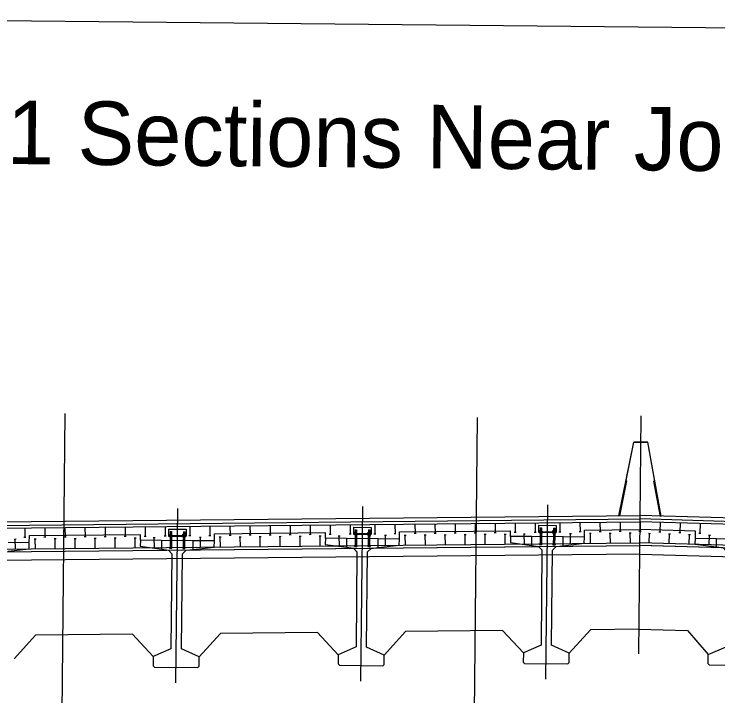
# Model space of a CAD drawing. Extents: x 632047 to 632524, y 378118 to 378491.
# Drawn here: x 632347.97 to 632381.26, y 378202.06 to 378234.31 of the extents above; entities that cross this region are included whole.
import ezdxf

# ---------------------------------------------------------------- set-up
doc = ezdxf.new("R2010")
doc.units = 0
for name, color, linetype in [('B_Boring', 7, 'Continuous'), ('B_Boring Annot', 7, 'Continuous'), ('B_No_Plot', 7, 'Continuous'), ('D_FEMA A', 7, 'Continuous'), ('R_Border_Divider', 7, 'Continuous'), ('R_Proposed Const Limits Cut', 7, 'Continuous'), ('R_Proposed Const Limits Fill', 7, 'Continuous'), ('R_Road Edge of Shoulder', 7, 'Continuous'), ('R_Shade Removal', 7, 'Continuous'), ('USACE_Easement', 7, 'Continuous'), ('USACE_Owned_Permited to Fort Chaffee', 7, 'Continuous')]:
    doc.layers.add(name, color=color, linetype=linetype)

msp = doc.modelspace()

# ---------------------------------------------------------------- linework, layer by layer
at = {"layer": 'B_Boring'}
for p, q in [((632376.625, 378210.569), (632376.958, 378212.231)), ((632376.918, 378212.239), (632376.958, 378212.231)), ((632378.28, 378212.226), (632378.239, 378212.218)), ((632378.539, 378210.55), (632378.239, 378212.218)), ((632336.245, 378210.015), (632377.581, 378210.428)), ((632336.493, 378210.184), (632377.582, 378210.597)), ((632418.9, 378209.19), (632377.581, 378210.428)), ((632418.655, 378209.364), (632377.583, 378210.597)), ((632336.575, 378209.887), (632377.579, 378210.299)), ((632372.783, 378210.127), (632372.78, 378209.797)), ((632372.783, 378210.127), (632373.616, 378210.118)), ((632373.616, 378210.118), (632373.613, 378209.789)), ((632418.567, 378209.069), (632377.58, 378210.299)), ((632355.28, 378209.951), (632355.277, 378209.621)), ((632355.28, 378209.951), (632356.114, 378209.942)), ((632356.114, 378209.942), (632356.11, 378209.613)), ((632364.032, 378210.039), (632364.028, 378209.709)), ((632364.032, 378210.039), (632364.865, 378210.03)), ((632364.075, 378209.757), (632364.197, 378209.756)), ((632364.075, 378209.742), (632364.075, 378209.757)), ((632364.084, 378209.796), (632364.188, 378209.795)), ((632364.084, 378209.757), (632364.084, 378209.796)), ((632364.188, 378209.756), (632364.188, 378209.795)), ((632364.197, 378209.741), (632364.197, 378209.756)), ((632364.7, 378209.751), (632364.822, 378209.75)), ((632364.7, 378209.736), (632364.7, 378209.751)), ((632364.709, 378209.79), (632364.813, 378209.789)), ((632364.709, 378209.751), (632364.709, 378209.79)), ((632364.813, 378209.75), (632364.813, 378209.789)), ((632364.822, 378209.735), (632364.822, 378209.75)), ((632364.865, 378210.03), (632364.862, 378209.701)), ((632372.78, 378209.831), (632373.613, 378209.822)), ((632372.78, 378209.797), (632373.613, 378209.789)), ((632372.826, 378209.797), (632372.825, 378209.782)), ((632372.825, 378209.782), (632372.948, 378209.781)), ((632372.826, 378209.845), (632372.949, 378209.844)), ((632372.826, 378209.83), (632372.826, 378209.845)), ((632372.826, 378209.83), (632372.948, 378209.829)), ((632372.826, 378209.797), (632372.948, 378209.796)), ((632372.835, 378209.782), (632372.834, 378209.743)), ((632372.835, 378209.845), (632372.836, 378209.884)), ((632372.836, 378209.884), (632372.94, 378209.883)), ((632372.939, 378209.781), (632372.938, 378209.742)), ((632372.939, 378209.844), (632372.94, 378209.883)), ((632372.948, 378209.829), (632372.949, 378209.844)), ((632372.948, 378209.796), (632372.948, 378209.781)), ((632373.451, 378209.791), (632373.45, 378209.776)), ((632373.45, 378209.776), (632373.573, 378209.775)), ((632373.451, 378209.839), (632373.573, 378209.838)), ((632373.451, 378209.824), (632373.451, 378209.839)), ((632373.451, 378209.824), (632373.573, 378209.823)), ((632373.451, 378209.791), (632373.573, 378209.789)), ((632373.46, 378209.776), (632373.459, 378209.737)), ((632373.46, 378209.839), (632373.461, 378209.878)), ((632373.461, 378209.878), (632373.565, 378209.877)), ((632373.564, 378209.775), (632373.563, 378209.736)), ((632373.564, 378209.838), (632373.565, 378209.877)), ((632373.573, 378209.823), (632373.573, 378209.838)), ((632373.573, 378209.789), (632373.573, 378209.775)), ((632355.277, 378209.655), (632356.111, 378209.646)), ((632355.277, 378209.621), (632356.11, 378209.613)), ((632355.323, 378209.669), (632355.446, 378209.668)), ((632355.323, 378209.654), (632355.323, 378209.669)), ((632355.323, 378209.654), (632355.446, 378209.653)), ((632355.323, 378209.621), (632355.323, 378209.606)), ((632355.323, 378209.621), (632355.445, 378209.62)), ((632355.323, 378209.606), (632355.445, 378209.605)), ((632355.332, 378209.606), (632355.332, 378209.567)), ((632355.332, 378209.567), (632355.436, 378209.566)), ((632355.333, 378209.708), (632355.437, 378209.707)), ((632355.333, 378209.669), (632355.333, 378209.708)), ((632355.436, 378209.605), (632355.436, 378209.566)), ((632355.437, 378209.668), (632355.437, 378209.707)), ((632355.445, 378209.62), (632355.445, 378209.605)), ((632355.446, 378209.653), (632355.446, 378209.668)), ((632355.948, 378209.663), (632356.071, 378209.662)), ((632355.948, 378209.648), (632355.948, 378209.663)), ((632355.948, 378209.648), (632356.071, 378209.647)), ((632355.948, 378209.615), (632355.948, 378209.6)), ((632355.948, 378209.615), (632356.07, 378209.613)), ((632355.948, 378209.6), (632356.07, 378209.599)), ((632355.957, 378209.6), (632355.957, 378209.561)), ((632355.957, 378209.561), (632356.061, 378209.56)), ((632355.958, 378209.702), (632356.062, 378209.701)), ((632355.958, 378209.663), (632355.958, 378209.702)), ((632356.061, 378209.599), (632356.061, 378209.56)), ((632356.062, 378209.662), (632356.062, 378209.701)), ((632356.07, 378209.613), (632356.07, 378209.599)), ((632356.071, 378209.647), (632356.071, 378209.662)), ((632364.028, 378209.709), (632364.862, 378209.701)), ((632364.029, 378209.743), (632364.862, 378209.734)), ((632364.074, 378209.709), (632364.074, 378209.694)), ((632364.074, 378209.709), (632364.197, 378209.708)), ((632364.074, 378209.694), (632364.197, 378209.693)), ((632364.075, 378209.742), (632364.197, 378209.741)), ((632364.083, 378209.694), (632364.083, 378209.655)), ((632364.083, 378209.655), (632364.187, 378209.654)), ((632364.187, 378209.693), (632364.187, 378209.654)), ((632364.197, 378209.708), (632364.197, 378209.693)), ((632364.699, 378209.703), (632364.699, 378209.688)), ((632364.699, 378209.703), (632364.822, 378209.701)), ((632364.699, 378209.688), (632364.822, 378209.687)), ((632364.7, 378209.736), (632364.822, 378209.735)), ((632364.708, 378209.688), (632364.708, 378209.649)), ((632364.708, 378209.649), (632364.812, 378209.648)), ((632364.812, 378209.687), (632364.812, 378209.648)), ((632364.822, 378209.701), (632364.822, 378209.687)), ((632372.834, 378209.743), (632372.938, 378209.742)), ((632373.459, 378209.737), (632373.563, 378209.736)), ((632336.587, 378208.768), (632377.593, 378209.178)), ((632336.591, 378208.892), (632377.569, 378209.304)), ((632336.593, 378208.768), (632377.568, 378209.18)), ((632418.533, 378207.951), (632377.543, 378209.178)), ((632418.527, 378207.951), (632377.568, 378209.18)), ((632418.532, 378208.075), (632377.569, 378209.304))]:
    msp.add_line(p, q, dxfattribs=at)
at = {"layer": 'B_Boring Annot'}
for p, q in [((632376.582, 378210.569), (632377.284, 378214.062)), ((632376.586, 378210.587), (632377.284, 378214.062)), ((632376.586, 378210.587), (632377.284, 378214.062)), ((632377.284, 378214.062), (632377.95, 378214.055)), ((632377.284, 378214.062), (632377.95, 378214.055)), ((632377.95, 378214.055), (632377.284, 378214.062)), ((632377.95, 378214.055), (632377.284, 378214.062)), ((632377.95, 378214.055), (632377.284, 378214.062)), ((632377.95, 378214.055), (632377.284, 378214.062)), ((632377.284, 378214.062), (632377.95, 378214.055)), ((632377.95, 378214.055), (632377.284, 378214.062)), ((632377.95, 378214.055), (632377.284, 378214.062)), ((632377.284, 378214.062), (632377.95, 378214.055)), ((632377.284, 378214.062), (632377.95, 378214.055)), ((632377.284, 378214.062), (632377.95, 378214.055)), ((632377.284, 378214.062), (632377.95, 378214.055)), ((632378.579, 378210.567), (632377.95, 378214.055)), ((632378.582, 378210.549), (632377.95, 378214.055)), ((632378.579, 378210.567), (632377.95, 378214.055)), ((632378.579, 378210.567), (632377.95, 378214.055)), ((632378.582, 378210.549), (632377.95, 378214.055)), ((632336.576, 378210.185), (632377.582, 378210.597)), ((632418.572, 378209.367), (632377.582, 378210.597)), ((632366.486, 378205.101), (632365.475, 378203.986)), ((632371.07, 378205.148), (632366.486, 378205.101)), ((632372.059, 378204.096), (632371.07, 378205.148)), ((632375.237, 378205.189), (632374.226, 378204.074)), ((632377.529, 378205.212), (632375.237, 378205.189)), ((632377.528, 378205.212), (632379.819, 378205.144)), ((632379.819, 378205.144), (632380.808, 378204.009)), ((632348.983, 378204.925), (632347.972, 378203.81)), ((632353.567, 378204.971), (632348.983, 378204.925)), ((632354.557, 378203.92), (632353.567, 378204.971)), ((632357.734, 378205.013), (632356.723, 378203.898)), ((632362.318, 378205.059), (632357.734, 378205.013)), ((632363.308, 378204.008), (632362.318, 378205.059))]:
    msp.add_line(p, q, dxfattribs=at)
at = {"layer": 'B_No_Plot'}
for p, q in [((632356.285, 378210.085), (632356.289, 378209.627)), ((632357.233, 378210.094), (632357.237, 378209.637)), ((632358.181, 378210.104), (632358.185, 378209.646)), ((632359.129, 378210.113), (632359.134, 378209.656)), ((632360.077, 378210.123), (632360.082, 378209.665)), ((632361.025, 378210.132), (632361.03, 378209.675)), ((632361.973, 378210.142), (632361.978, 378209.684)), ((632362.921, 378210.152), (632362.926, 378209.694)), ((632363.869, 378210.161), (632363.874, 378209.703)), ((632365.036, 378210.173), (632365.041, 378209.715)), ((632365.984, 378210.182), (632365.989, 378209.725)), ((632366.932, 378210.192), (632366.937, 378209.734)), ((632367.88, 378210.201), (632367.885, 378209.744)), ((632368.828, 378210.211), (632368.833, 378209.753)), ((632369.776, 378210.22), (632369.781, 378209.763)), ((632370.725, 378210.23), (632370.729, 378209.772)), ((632371.673, 378210.24), (632371.677, 378209.782)), ((632372.621, 378210.249), (632372.625, 378209.791)), ((632373.787, 378210.261), (632373.792, 378209.803)), ((632374.735, 378210.27), (632374.74, 378209.813)), ((632375.683, 378210.28), (632375.688, 378209.822)), ((632376.632, 378210.289), (632376.636, 378209.832)), ((632377.579, 378210.299), (632377.565, 378209.841)), ((632377.579, 378210.299), (632377.565, 378209.841)), ((632377.58, 378210.299), (632377.584, 378209.841)), ((632377.58, 378210.299), (632377.584, 378209.841)), ((632378.527, 378210.271), (632378.513, 378209.813)), ((632379.475, 378210.242), (632379.461, 378209.785)), ((632380.422, 378210.214), (632380.409, 378209.756)), ((632348.481, 378210.006), (632348.486, 378209.549)), ((632349.43, 378210.016), (632349.434, 378209.558)), ((632350.378, 378210.025), (632350.382, 378209.568)), ((632351.326, 378210.035), (632351.33, 378209.577)), ((632352.274, 378210.044), (632352.278, 378209.587)), ((632353.222, 378210.054), (632353.227, 378209.596)), ((632354.17, 378210.064), (632354.175, 378209.606)), ((632355.118, 378210.073), (632355.123, 378209.615)), ((632367.932, 378209.744), (632367.838, 378209.743)), ((632368.88, 378209.754), (632368.786, 378209.753)), ((632369.828, 378209.763), (632369.734, 378209.762)), ((632370.776, 378209.773), (632370.682, 378209.772)), ((632371.724, 378209.782), (632371.63, 378209.781)), ((632372.672, 378209.792), (632372.578, 378209.791)), ((632373.839, 378209.804), (632373.745, 378209.803)), ((632374.787, 378209.813), (632374.693, 378209.812)), ((632375.735, 378209.823), (632375.641, 378209.822)), ((632376.219, 378209.748), (632376.126, 378209.747)), ((632376.177, 378209.29), (632376.173, 378209.748)), ((632376.683, 378209.832), (632376.589, 378209.831)), ((632377.164, 378209.758), (632377.07, 378209.757)), ((632377.121, 378209.3), (632377.117, 378209.757)), ((632377.519, 378209.843), (632377.612, 378209.84)), ((632377.519, 378209.843), (632377.612, 378209.84)), ((632377.631, 378209.842), (632377.537, 378209.841)), ((632377.631, 378209.842), (632377.537, 378209.841)), ((632377.984, 378209.75), (632378.078, 378209.747)), ((632378.017, 378209.291), (632378.031, 378209.748)), ((632378.466, 378209.814), (632378.56, 378209.812)), ((632379.414, 378209.786), (632379.508, 378209.783)), ((632380.362, 378209.757), (632380.455, 378209.755)), ((632348.077, 378209.465), (632347.983, 378209.464)), ((632348.035, 378209.007), (632348.03, 378209.465)), ((632348.533, 378209.549), (632348.439, 378209.548)), ((632349.021, 378209.475), (632348.928, 378209.474)), ((632348.979, 378209.017), (632348.974, 378209.474)), ((632349.481, 378209.559), (632349.387, 378209.558)), ((632349.965, 378209.484), (632349.872, 378209.483)), ((632349.923, 378209.026), (632349.919, 378209.484)), ((632350.429, 378209.568), (632350.335, 378209.567)), ((632350.91, 378209.494), (632350.816, 378209.493)), ((632350.867, 378209.036), (632350.863, 378209.493)), ((632351.377, 378209.578), (632351.283, 378209.577)), ((632351.854, 378209.503), (632351.76, 378209.502)), ((632351.812, 378209.045), (632351.807, 378209.503)), ((632352.325, 378209.587), (632352.232, 378209.586)), ((632352.798, 378209.513), (632352.704, 378209.512)), ((632352.756, 378209.055), (632352.751, 378209.512)), ((632353.273, 378209.597), (632353.18, 378209.596)), ((632353.742, 378209.522), (632353.648, 378209.521)), ((632353.7, 378209.064), (632353.695, 378209.522)), ((632354.221, 378209.606), (632354.128, 378209.605)), ((632354.65, 378209.531), (632354.557, 378209.531)), ((632354.608, 378209.073), (632354.603, 378209.531)), ((632355.17, 378209.616), (632355.076, 378209.615)), ((632356.336, 378209.628), (632356.242, 378209.627)), ((632356.828, 378209.553), (632356.735, 378209.552)), ((632356.786, 378209.095), (632356.782, 378209.553)), ((632357.284, 378209.637), (632357.19, 378209.636)), ((632357.773, 378209.563), (632357.679, 378209.562)), ((632357.73, 378209.105), (632357.726, 378209.562)), ((632358.232, 378209.647), (632358.139, 378209.646)), ((632358.717, 378209.572), (632358.623, 378209.571)), ((632358.675, 378209.114), (632358.67, 378209.572)), ((632359.18, 378209.656), (632359.087, 378209.655)), ((632359.661, 378209.582), (632359.567, 378209.581)), ((632359.619, 378209.124), (632359.614, 378209.581)), ((632360.129, 378209.666), (632360.035, 378209.665)), ((632360.605, 378209.591), (632360.511, 378209.59)), ((632360.563, 378209.133), (632360.558, 378209.591)), ((632361.077, 378209.675), (632360.983, 378209.674)), ((632361.549, 378209.601), (632361.456, 378209.6)), ((632361.507, 378209.143), (632361.502, 378209.6)), ((632362.025, 378209.685), (632361.931, 378209.684)), ((632362.494, 378209.61), (632362.4, 378209.609)), ((632362.451, 378209.152), (632362.447, 378209.61)), ((632362.973, 378209.694), (632362.879, 378209.693)), ((632363.402, 378209.619), (632363.308, 378209.619)), ((632363.359, 378209.161), (632363.355, 378209.619)), ((632363.921, 378209.704), (632363.827, 378209.703)), ((632365.087, 378209.716), (632364.994, 378209.715)), ((632365.58, 378209.641), (632365.486, 378209.64)), ((632365.537, 378209.183), (632365.533, 378209.641)), ((632366.036, 378209.725), (632365.942, 378209.724)), ((632366.524, 378209.651), (632366.43, 378209.65)), ((632366.482, 378209.193), (632366.477, 378209.65)), ((632366.984, 378209.735), (632366.89, 378209.734)), ((632367.468, 378209.66), (632367.374, 378209.659)), ((632367.426, 378209.202), (632367.421, 378209.66)), ((632368.412, 378209.67), (632368.319, 378209.669)), ((632368.37, 378209.212), (632368.365, 378209.669)), ((632369.356, 378209.679), (632369.263, 378209.678)), ((632369.314, 378209.221), (632369.31, 378209.679)), ((632370.301, 378209.689), (632370.207, 378209.688)), ((632370.258, 378209.231), (632370.254, 378209.688)), ((632371.245, 378209.698), (632371.151, 378209.697)), ((632371.203, 378209.24), (632371.198, 378209.698)), ((632372.153, 378209.707), (632372.059, 378209.707)), ((632372.111, 378209.249), (632372.106, 378209.707)), ((632374.331, 378209.729), (632374.237, 378209.728)), ((632374.289, 378209.271), (632374.284, 378209.729)), ((632375.275, 378209.739), (632375.181, 378209.738)), ((632375.233, 378209.281), (632375.228, 378209.738)), ((632378.928, 378209.721), (632379.022, 378209.719)), ((632378.961, 378209.262), (632378.975, 378209.72)), ((632379.872, 378209.693), (632379.966, 378209.69)), ((632379.905, 378209.234), (632379.919, 378209.692)), ((632380.816, 378209.665), (632380.909, 378209.662)), ((632380.849, 378209.206), (632380.863, 378209.663))]:
    msp.add_line(p, q, dxfattribs=at)
at = {"layer": 'D_FEMA A'}
for p, q in [((632350.379, 378215.413), (632349.969, 378174.214)), ((632369.878, 378215.22), (632369.468, 378174.021))]:
    msp.add_line(p, q, dxfattribs=at)
at = {"layer": 'R_Border_Divider'}
for p, q in [((632357.448, 378209.728), (632362.699, 378209.781)), ((632362.696, 378209.514), (632362.699, 378209.781)), ((632366.196, 378209.479), (632366.199, 378209.816)), ((632366.199, 378209.816), (632371.45, 378209.869)), ((632371.447, 378209.602), (632371.45, 378209.869)), ((632374.947, 378209.567), (632374.95, 378209.904)), ((632374.95, 378209.904), (632377.576, 378209.93)), ((632380.2, 378209.851), (632377.576, 378209.93)), ((632380.197, 378209.515), (632380.2, 378209.851)), ((632348.693, 378209.303), (632348.696, 378209.64)), ((632348.696, 378209.64), (632353.947, 378209.693)), ((632353.945, 378209.426), (632353.947, 378209.693)), ((632357.444, 378209.391), (632357.448, 378209.728)), ((632377.564, 378208.77), (632336.272, 378208.355)), ((632377.564, 378208.77), (632418.84, 378207.531))]:
    msp.add_line(p, q, dxfattribs=at)
for points in [[(632354.945, 378209.416), (632353.945, 378209.426), (632353.942, 378209.135), (632354.941, 378209)], [(632363.696, 378209.504), (632362.696, 378209.514), (632362.693, 378209.223), (632363.692, 378209.088)], [(632365.192, 378209.073), (632366.193, 378209.188), (632366.196, 378209.479), (632365.196, 378209.489)], [(632372.447, 378209.592), (632371.447, 378209.602), (632371.445, 378209.311), (632372.443, 378209.176)], [(632373.943, 378209.161), (632374.944, 378209.276), (632374.947, 378209.567), (632373.947, 378209.577)], [(632381.192, 378209.088), (632380.194, 378209.223), (632380.196, 378209.515), (632381.196, 378209.505)], [(632347.689, 378208.897), (632348.69, 378209.012), (632348.693, 378209.303), (632347.693, 378209.313)], [(632356.44, 378208.985), (632357.442, 378209.1), (632357.445, 378209.391), (632356.445, 378209.401)]]:
    msp.add_lwpolyline(points, dxfattribs=at)
at = {"layer": 'R_Proposed Const Limits Cut'}
for p, q in [((632355.351, 378209.412), (632355.348, 378209.079)), ((632355.413, 378209.412), (632355.41, 378209.078)), ((632364.102, 378209.5), (632364.099, 378209.167)), ((632364.165, 378209.5), (632364.161, 378209.166)), ((632364.727, 378209.494), (632364.724, 378209.161)), ((632364.79, 378209.493), (632364.786, 378209.16)), ((632372.853, 378209.588), (632372.85, 378209.255)), ((632372.916, 378209.588), (632372.913, 378209.254)), ((632373.478, 378209.582), (632373.475, 378209.249)), ((632373.541, 378209.581), (632373.538, 378209.248)), ((632355.327, 378209.079), (632355.326, 378209.04)), ((632355.327, 378209.079), (632355.431, 378209.078)), ((632355.431, 378209.078), (632355.431, 378209.039)), ((632355.976, 378209.406), (632355.973, 378209.073)), ((632356.038, 378209.405), (632356.035, 378209.072)), ((632364.078, 378209.167), (632364.182, 378209.166)), ((632364.078, 378209.167), (632364.078, 378209.128)), ((632364.078, 378209.128), (632364.182, 378209.127)), ((632364.182, 378209.166), (632364.182, 378209.127)), ((632364.703, 378209.161), (632364.807, 378209.16)), ((632364.703, 378209.161), (632364.703, 378209.122)), ((632364.703, 378209.122), (632364.807, 378209.121)), ((632364.807, 378209.16), (632364.807, 378209.121)), ((632372.829, 378209.255), (632372.934, 378209.254)), ((632372.829, 378209.255), (632372.829, 378209.216)), ((632372.829, 378209.216), (632372.933, 378209.215)), ((632372.934, 378209.254), (632372.933, 378209.215)), ((632373.454, 378209.249), (632373.558, 378209.248)), ((632373.454, 378209.249), (632373.454, 378209.21)), ((632373.454, 378209.21), (632373.558, 378209.209)), ((632373.558, 378209.248), (632373.558, 378209.209)), ((632355.326, 378209.04), (632355.431, 378209.039)), ((632355.952, 378209.073), (632355.951, 378209.034)), ((632355.951, 378209.034), (632356.055, 378209.033)), ((632355.952, 378209.073), (632356.056, 378209.072)), ((632356.056, 378209.072), (632356.055, 378209.033))]:
    msp.add_line(p, q, dxfattribs=at)
at = {"layer": 'R_Proposed Const Limits Fill'}
for p, q in [((632377.529, 378205.212), (632375.237, 378205.189)), ((632377.528, 378205.212), (632379.819, 378205.144))]:
    msp.add_line(p, q, dxfattribs=at)
at = {"layer": 'R_Road Edge of Shoulder'}
msp.add_line((632377.517, 378204.042), (632377.629, 378215.309), dxfattribs=at)
at = {"layer": 'R_Shade Removal'}
for p, q in [((632373.13, 378202.847), (632373.212, 378211.099)), ((632355.628, 378202.671), (632355.71, 378210.923)), ((632364.379, 378202.759), (632364.461, 378211.011))]:
    msp.add_line(p, q, dxfattribs=at)
at = {"layer": 'USACE_Easement'}
msp.add_lwpolyline([(632316.899, 378234.313), (632447.637, 378233.013), (632446.494, 378118.108), (632315.757, 378119.408)], close=True, dxfattribs=at)
at = {"layer": 'USACE_Owned_Permited to Fort Chaffee'}
for p, q in [((632355.355, 378209.829), (632355.354, 378209.708)), ((632355.355, 378209.829), (632355.418, 378209.829)), ((632355.418, 378209.829), (632355.416, 378209.707)), ((632355.98, 378209.823), (632355.979, 378209.702)), ((632355.98, 378209.823), (632356.042, 378209.822)), ((632356.042, 378209.822), (632356.041, 378209.701)), ((632364.106, 378209.917), (632364.105, 378209.796)), ((632364.106, 378209.917), (632364.169, 378209.917)), ((632364.169, 378209.917), (632364.168, 378209.795)), ((632364.731, 378209.911), (632364.73, 378209.79)), ((632364.731, 378209.911), (632364.794, 378209.91)), ((632364.794, 378209.91), (632364.793, 378209.789)), ((632372.858, 378210.005), (632372.856, 378209.884)), ((632372.858, 378210.005), (632372.92, 378210.005)), ((632372.92, 378210.005), (632372.919, 378209.883)), ((632373.48, 378209.776), (632373.478, 378209.582)), ((632373.483, 378209.999), (632373.481, 378209.878)), ((632373.483, 378209.999), (632373.545, 378209.998)), ((632373.543, 378209.775), (632373.541, 378209.581)), ((632373.545, 378209.998), (632373.544, 378209.877)), ((632354.945, 378209.416), (632354.941, 378209)), ((632355.352, 378209.567), (632355.351, 378209.412)), ((632355.415, 378209.566), (632355.413, 378209.412)), ((632355.978, 378209.6), (632355.976, 378209.406)), ((632356.04, 378209.599), (632356.038, 378209.405)), ((632363.696, 378209.504), (632363.692, 378209.088)), ((632364.104, 378209.655), (632364.102, 378209.5)), ((632364.166, 378209.654), (632364.165, 378209.5)), ((632364.729, 378209.688), (632364.727, 378209.494)), ((632364.792, 378209.687), (632364.79, 378209.493)), ((632365.192, 378209.073), (632365.196, 378209.489)), ((632372.447, 378209.592), (632372.443, 378209.176)), ((632372.855, 378209.743), (632372.853, 378209.588)), ((632372.918, 378209.742), (632372.916, 378209.588)), ((632373.943, 378209.161), (632373.947, 378209.577)), ((632381.192, 378209.088), (632381.196, 378209.505)), ((632356.44, 378208.985), (632356.445, 378209.401))]:
    msp.add_line(p, q, dxfattribs=at)
for points in [[(632356.445, 378209.401), (632354.945, 378209.416)], [(632365.196, 378209.489), (632363.696, 378209.504)], [(632373.947, 378209.577), (632372.447, 378209.592)], [(632381.196, 378209.505), (632382.696, 378209.49)], [(632363.692, 378209.088), (632364.025, 378209.043), (632364.19, 378208.874), (632364.145, 378204.375), (632363.308, 378204.008), (632363.304, 378203.57), (632363.365, 378203.507), (632365.407, 378203.487), (632365.47, 378203.549), (632365.475, 378203.986), (632364.645, 378204.37), (632364.69, 378208.869), (632364.858, 378209.034), (632365.192, 378209.073)], [(632372.443, 378209.176), (632372.776, 378209.131), (632372.941, 378208.962), (632372.896, 378204.463), (632372.059, 378204.096), (632372.055, 378203.658), (632372.117, 378203.595), (632374.158, 378203.575), (632374.221, 378203.637), (632374.226, 378204.074), (632373.396, 378204.458), (632373.441, 378208.957), (632373.609, 378209.122), (632373.943, 378209.161)], [(632382.692, 378209.073), (632382.358, 378209.035), (632382.19, 378208.87), (632382.145, 378204.37), (632382.975, 378203.987), (632382.97, 378203.55), (632382.907, 378203.488), (632380.866, 378203.508), (632380.804, 378203.571), (632380.808, 378204.009), (632381.645, 378204.375), (632381.69, 378208.875), (632381.525, 378209.043), (632381.192, 378209.088)], [(632354.941, 378209), (632355.273, 378208.955), (632355.438, 378208.786), (632355.394, 378204.287), (632354.557, 378203.92), (632354.552, 378203.482), (632354.614, 378203.419), (632356.656, 378203.399), (632356.719, 378203.461), (632356.723, 378203.898), (632355.894, 378204.282), (632355.938, 378208.781), (632356.107, 378208.946), (632356.44, 378208.985)]]:
    msp.add_lwpolyline(points, dxfattribs=at)

# ---------------------------------------------------------------- texts
at = {"layer": 'USACE_Easement'}
msp.add_text('Alternate No. 1 Sections Near Joints (Strip and Finger Shown)', height=3, rotation=359.4304, dxfattribs=at).set_placement((632323.093, 378227.466))

doc.saveas('drawing.dxf')
